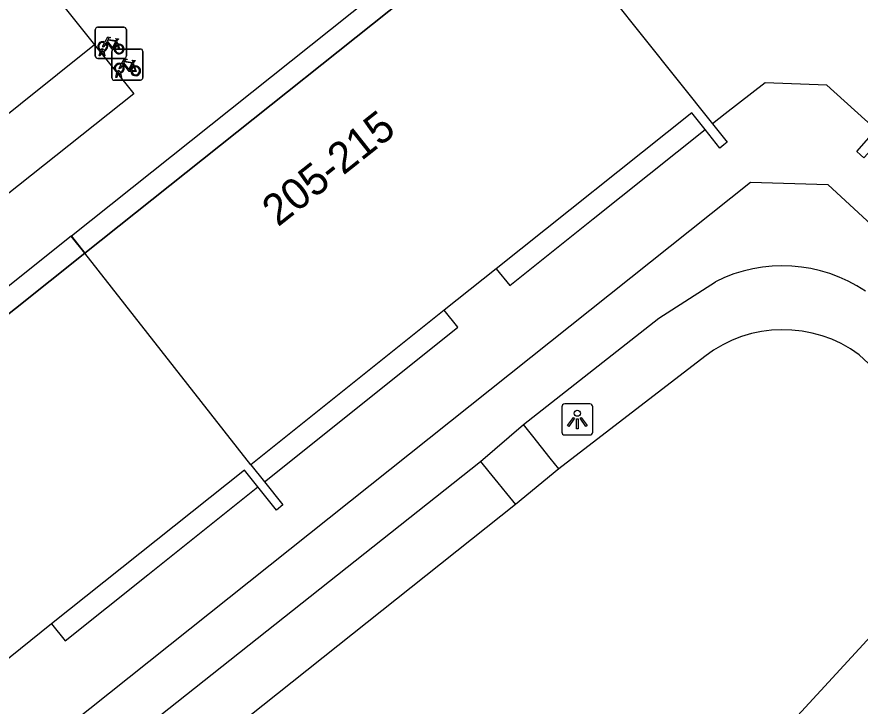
# Model space of a CAD drawing. Extents: x 159040 to 160094, y 381214 to 382518.
# Drawn here: x 159593.38 to 159620.49, y 381725.95 to 381748.12 of the extents above; entities that cross this region are included whole.
import ezdxf

# ---------------------------------------------------------------- set-up
doc = ezdxf.new("R2010")
doc.units = 0
for name, color, linetype in [('IMGEO_Fietsenrek', 7, 'Continuous'), ('IMGEO_Haag', 7, 'Continuous'), ('IMGEO_Lichtpunt', 7, 'Continuous'), ('IMGEO_Pand', 7, 'Continuous'), ('IMGEO_Pand_nummerreeks', 7, 'Continuous'), ('IMGEO_Pand_overbouw', 7, 'Continuous'), ('IMGEO_Voetpad_gesloten', 7, 'Continuous'), ('IMGEO_Voetpad_open', 7, 'Continuous')]:
    doc.layers.add(name, color=color, linetype=linetype)

msp = doc.modelspace()

# ---------------------------------------------------------------- linework, layer by layer
at = {"layer": 'IMGEO_Fietsenrek'}
for p, q in [((159595.902, 381746.858), (159595.902, 381747.699)), ((159595.902, 381747.699), (159595.902, 381746.858)), ((159595.977, 381747.783), (159596.818, 381747.783)), ((159596.818, 381747.783), (159595.977, 381747.783)), ((159596.902, 381747.708), (159596.902, 381746.867)), ((159596.902, 381746.867), (159596.902, 381747.708)), ((159596.589, 381747.332), (159596.625, 381747.237)), ((159596.029, 381746.867), (159596.068, 381747.027)), ((159596.14, 381747.039), (159596.139, 381747.043)), ((159596.171, 381747.05), (159596.172, 381747.043)), ((159596.508, 381747.083), (159597.349, 381747.083)), ((159597.349, 381747.083), (159596.508, 381747.083)), ((159596.827, 381746.783), (159595.986, 381746.783)), ((159595.986, 381746.783), (159596.827, 381746.783)), ((159596.063, 381746.867), (159596.029, 381746.867)), ((159596.098, 381747.015), (159596.063, 381746.867)), ((159596.181, 381746.867), (159596.147, 381747.009)), ((159596.179, 381747.013), (159596.214, 381746.867)), ((159596.214, 381746.867), (159596.181, 381746.867)), ((159596.433, 381746.158), (159596.433, 381746.999)), ((159596.433, 381746.999), (159596.433, 381746.158)), ((159597.433, 381747.008), (159597.433, 381746.167)), ((159597.433, 381746.167), (159597.433, 381747.008)), ((159597.12, 381746.632), (159597.156, 381746.537)), ((159596.56, 381746.167), (159596.599, 381746.327)), ((159596.629, 381746.315), (159596.594, 381746.167)), ((159596.671, 381746.339), (159596.67, 381746.343)), ((159596.712, 381746.167), (159596.678, 381746.309)), ((159596.702, 381746.35), (159596.703, 381746.343)), ((159596.71, 381746.313), (159596.745, 381746.167)), ((159597.358, 381746.083), (159596.517, 381746.083)), ((159596.517, 381746.083), (159597.358, 381746.083)), ((159596.594, 381746.167), (159596.56, 381746.167)), ((159596.745, 381746.167), (159596.712, 381746.167))]:
    msp.add_line(p, q, dxfattribs=at)
for points in [[(159596.215, 381747.309), (159596.31, 381747.473), (159596.396, 381747.459), (159596.398, 381747.45), (159596.342, 381747.439), (159596.315, 381747.394), (159596.571, 381747.353)], [(159596.511, 381747.065), (159596.461, 381747.065), (159596.27, 381747.316), (159596.251, 381747.284)], [(159596.558, 381747.328), (159596.301, 381747.369), (159596.284, 381747.34), (159596.451, 381747.12), (159596.558, 381747.328)], [(159596.606, 381747.23), (159596.576, 381747.307), (159596.467, 381747.089), (159596.51, 381747.089)], [(159596.571, 381747.353), (159596.596, 381747.402), (159596.59, 381747.406), (159596.567, 381747.41), (159596.555, 381747.417), (159596.554, 381747.42), (159596.556, 381747.425), (159596.651, 381747.41), (159596.653, 381747.4), (159596.643, 381747.387), (159596.631, 381747.381), (159596.617, 381747.387), (159596.589, 381747.332)], [(159596.236, 381747.257), (159596.184, 381747.167), (159596.144, 381747.142), (159596.145, 381747.189), (159596.2, 381747.283)], [(159596.54, 381747.089), (159596.66, 381747.088), (159596.616, 381747.202)], [(159596.636, 381747.209), (159596.691, 381747.064), (159596.541, 381747.064)], [(159596.746, 381746.609), (159596.841, 381746.773), (159596.927, 381746.759), (159596.929, 381746.75), (159596.873, 381746.739), (159596.846, 381746.694), (159597.102, 381746.653)], [(159596.767, 381746.557), (159596.715, 381746.467), (159596.675, 381746.442), (159596.676, 381746.489), (159596.731, 381746.583)], [(159597.042, 381746.365), (159596.992, 381746.365), (159596.801, 381746.616), (159596.782, 381746.584)], [(159597.089, 381746.628), (159596.832, 381746.669), (159596.815, 381746.64), (159596.982, 381746.42), (159597.089, 381746.628)], [(159597.137, 381746.53), (159597.107, 381746.607), (159596.998, 381746.389), (159597.041, 381746.389)], [(159597.071, 381746.389), (159597.191, 381746.388), (159597.147, 381746.502)], [(159597.167, 381746.509), (159597.222, 381746.364), (159597.072, 381746.364)], [(159597.102, 381746.653), (159597.127, 381746.702), (159597.121, 381746.706), (159597.098, 381746.71), (159597.086, 381746.717), (159597.085, 381746.72), (159597.087, 381746.725), (159597.182, 381746.71), (159597.184, 381746.7), (159597.174, 381746.687), (159597.162, 381746.681), (159597.148, 381746.687), (159597.12, 381746.632)]]:
    msp.add_lwpolyline(points, dxfattribs=at)
for centre, radius, start, end in [((159595.98, 381747.705), 0.0779, 92.4484, 184.2845), ((159595.98, 381747.705), 0.0779, 92.4484, 184.2845), ((159596.824, 381747.705), 0.0779, 2.4484, 94.2845), ((159596.824, 381747.705), 0.0779, 2.4484, 94.2845), ((159596.142, 381747.168), 0.159, 62.6766, 242.1369), ((159596.142, 381747.168), 0.129, 63.3192, 238.903), ((159596.122, 381747.039), 0.0499, 12.8025, 158.6934), ((159596.122, 381747.039), 0.0174, 12.8025, 163.4502), ((159596.142, 381747.168), 0.129, 253.415, 269.0204), ((159596.142, 381747.168), 0.129, 283.6043, 43.4302), ((159596.142, 381747.168), 0.159, 283.5766, 46.6042), ((159596.511, 381747.005), 0.0779, 92.4484, 184.2845), ((159596.511, 381747.005), 0.0779, 92.4484, 184.2845), ((159596.669, 381747.084), 0.159, 113.3408, 178.3217), ((159596.669, 381747.084), 0.159, 187.0065, 105.7708), ((159596.669, 381747.084), 0.129, 113.923, 177.9556), ((159596.669, 381747.084), 0.129, 188.6715, 104.5883), ((159597.355, 381747.005), 0.0779, 2.4484, 94.2845), ((159597.355, 381747.005), 0.0779, 2.4484, 94.2845), ((159595.98, 381746.861), 0.0779, 182.4484, 274.2845), ((159595.98, 381746.861), 0.0779, 182.4484, 274.2845), ((159596.142, 381747.168), 0.159, 253.9967, 271.7867), ((159596.824, 381746.861), 0.0779, 272.4484, 4.2845), ((159596.824, 381746.861), 0.0779, 272.4484, 4.2845), ((159596.673, 381746.468), 0.159, 62.6766, 242.1369), ((159596.673, 381746.468), 0.129, 63.3192, 238.903), ((159596.673, 381746.468), 0.129, 283.6043, 43.4302), ((159596.673, 381746.468), 0.159, 283.5766, 46.6042), ((159597.2, 381746.384), 0.159, 113.3408, 178.3217), ((159597.2, 381746.384), 0.159, 187.0065, 105.7708), ((159597.2, 381746.384), 0.129, 113.923, 177.9556), ((159597.2, 381746.384), 0.129, 188.6715, 104.5883), ((159596.653, 381746.339), 0.0499, 12.8025, 158.6934), ((159596.673, 381746.468), 0.159, 253.9967, 271.7867), ((159596.653, 381746.339), 0.0174, 12.8025, 163.4502), ((159596.673, 381746.468), 0.129, 253.415, 269.0204), ((159596.511, 381746.161), 0.0779, 182.4484, 274.2845), ((159596.511, 381746.161), 0.0779, 182.4484, 274.2845), ((159597.355, 381746.161), 0.0779, 272.4484, 4.2845), ((159597.355, 381746.161), 0.0779, 272.4484, 4.2845)]:
    msp.add_arc(centre, radius, start, end, dxfattribs=at)
at = {"layer": 'IMGEO_Haag'}
for points in [[(159595.879, 381747.215), (159585.166, 381738.629)], [(159615.498, 381737.198), (159610.8, 381733.576)], [(159625.148, 381732.892), (159620.456, 381737.249)], [(159609.407, 381732.434), (159596.519, 381722.173)]]:
    msp.add_lwpolyline(points, dxfattribs=at)
msp.add_arc((159618.011, 381733.949), 4.107, 53.4629, 127.7158, dxfattribs=at)
at = {"layer": 'IMGEO_Lichtpunt'}
for p, q in [((159611.8, 381735.667), (159610.992, 381735.667)), ((159611.8, 381735.667), (159610.992, 381735.667)), ((159610.898, 381735.572), (159610.898, 381734.765)), ((159610.898, 381735.572), (159610.898, 381734.765)), ((159611.894, 381734.765), (159611.894, 381735.572)), ((159611.894, 381734.765), (159611.894, 381735.572)), ((159610.992, 381734.671), (159611.8, 381734.671)), ((159610.992, 381734.671), (159611.8, 381734.671))]:
    msp.add_line(p, q, dxfattribs=at)
for points in [[(159611.272, 381735.236), (159611.311, 381735.208), (159611.123, 381734.946), (159611.085, 381734.973), (159611.272, 381735.236)], [(159611.374, 381735.188), (159611.421, 381735.188), (159611.421, 381734.866), (159611.374, 381734.866), (159611.374, 381735.188)], [(159611.484, 381735.208), (159611.522, 381735.235), (159611.709, 381734.973), (159611.67, 381734.945), (159611.484, 381735.208)]]:
    msp.add_lwpolyline(points, dxfattribs=at)
msp.add_circle((159611.397, 381735.37), 0.0994, dxfattribs=at)
for centre, start, end in [((159610.992, 381735.572), 90, 180), ((159610.992, 381735.572), 90, 180), ((159611.8, 381735.572), 0, 90), ((159611.8, 381735.572), 0, 90), ((159610.992, 381734.765), 180, 270), ((159610.992, 381734.765), 180, 270), ((159611.8, 381734.765), 270, 0), ((159611.8, 381734.765), 270, 360)]:
    msp.add_arc(centre, 0.0946, start, end, dxfattribs=at)
at = {"layer": 'IMGEO_Pand'}
for points in [[(159610.269, 381751.55), (159609.49, 381752.522), (159609.258, 381752.335), (159609.699, 381751.791), (159595.564, 381740.514)], [(159610.269, 381751.55), (159615.741, 381744.679)], [(159621, 381744.494), (159620.641, 381744.818), (159619.416, 381745.923), (159617.434, 381745.992), (159616.149, 381744.995), (159615.741, 381744.679)], [(159615.741, 381744.679), (159616.213, 381744.085), (159616.102, 381743.997), (159615.978, 381743.898), (159615.502, 381744.497), (159615.074, 381745.036), (159608.793, 381740.018), (159607.119, 381738.682), (159600.899, 381733.713)], [(159633.856, 381731.046), (159633.773, 381731.121), (159634.413, 381731.817), (159634.886, 381732.329), (159629.072, 381737.715), (159627.49, 381739.181), (159621.587, 381744.649), (159621.114, 381744.136), (159620.607, 381743.587), (159620.499, 381743.683), (159620.377, 381743.791), (159621, 381744.494)], [(159595.564, 381740.514), (159581.175, 381729.034)], [(159600.899, 381733.713), (159595.564, 381740.514)], [(159600.899, 381733.713), (159601.338, 381733.163), (159601.932, 381732.42), (159601.724, 381732.25), (159601.131, 381732.998), (159600.7, 381733.542), (159594.499, 381728.591), (159592.826, 381727.256), (159586.593, 381722.28)]]:
    msp.add_lwpolyline(points, dxfattribs=at)
at = {"layer": 'IMGEO_Pand_overbouw'}
for points in [[(159609.258, 381752.335), (159595.136, 381741.061), (159595.564, 381740.514), (159609.699, 381751.791)], [(159608.793, 381740.018), (159609.225, 381739.477), (159611.909, 381741.624), (159615.502, 381744.497), (159615.074, 381745.036)], [(159581.175, 381729.034), (159595.564, 381740.514), (159595.131, 381741.067), (159580.744, 381729.571)], [(159607.119, 381738.682), (159600.899, 381733.713), (159601.338, 381733.163), (159604.864, 381735.982), (159607.557, 381738.134)], [(159594.499, 381728.591), (159594.936, 381728.045), (159597.596, 381730.171), (159601.131, 381732.998), (159600.7, 381733.542)]]:
    msp.add_lwpolyline(points, close=True, dxfattribs=at)
at = {"layer": 'IMGEO_Voetpad_gesloten'}
for points in [[(159573.794, 381708.392), (159616.964, 381742.797), (159619.451, 381742.729), (159647.604, 381716.715)], [(159609.67, 381735.005), (159614.019, 381738.428), (159615.837, 381739.6)], [(159608.282, 381733.821), (159609.67, 381735.005)], [(159595.379, 381723.576), (159608.282, 381733.821)]]:
    msp.add_lwpolyline(points, dxfattribs=at)
msp.add_arc((159617.987, 381735.317), 4.792, 56.1683, 116.6583, dxfattribs=at)
at = {"layer": 'IMGEO_Voetpad_open'}
for points in [[(159591.503, 381752.685), (159595.879, 381747.215)], [(159595.879, 381747.215), (159597.139, 381745.64), (159586.379, 381737.091), (159585.166, 381738.629)], [(159610.8, 381733.576), (159610.521, 381733.929), (159610.241, 381734.282), (159609.962, 381734.635), (159609.67, 381735.005)], [(159608.282, 381733.821), (159608.557, 381733.482), (159608.84, 381733.133), (159609.124, 381732.783), (159609.407, 381732.434)], [(159610.8, 381733.576), (159609.407, 381732.434)], [(159615.517, 381722.415), (159625.148, 381732.892)]]:
    msp.add_lwpolyline(points, dxfattribs=at)

# ---------------------------------------------------------------- texts
at = {"layer": 'IMGEO_Pand_nummerreeks'}
msp.add_text('205-215', height=1, rotation=38.4029, dxfattribs=at).set_placement((159601.776, 381741.345))

doc.saveas('drawing.dxf')
